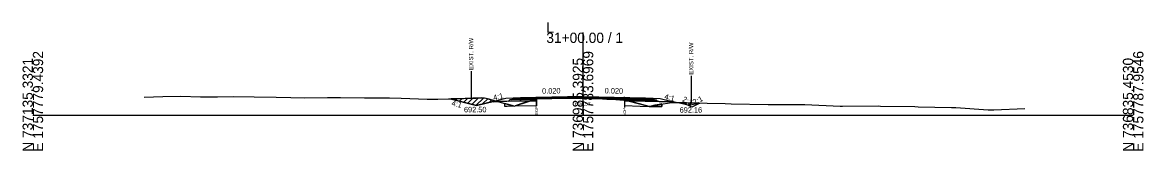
# Model space of a CAD drawing. Extents: x -26 to 4303, y -10 to 9577.
# Drawn here: x 1997.2 to 2302.8, y 990.3 to 1025.3 of the extents above; entities that cross this region are included whole.
import ezdxf

# ---------------------------------------------------------------- set-up
doc = ezdxf.new("R2010")
doc.units = 0
for name, color, linetype in [('Default', 7, 'Continuous'), ('Exist CMT Pavement', 7, 'Continuous'), ('Old_Level_10', 7, 'Continuous'), ('Old_Level_2', 7, 'Continuous'), ('Pattern 1', 7, 'Continuous'), ('Prop CMT Conc Surface', 7, 'Continuous'), ('Prop CMT Concrete Structures', 7, 'Continuous'), ('Prop CMT Concrete Wall', 7, 'Continuous'), ('Prop CMT Pvmt Course 1', 7, 'Continuous'), ('Prop CMT Pvmt Course 1 CG', 7, 'Continuous'), ('Prop CMT Pvmt Course 1 Wedge', 7, 'Continuous'), ('Prop CMT Pvmt Course 2', 7, 'Continuous'), ('Prop CMT Pvmt Course 2 Wedge', 7, 'Continuous'), ('Prop CMT Pvmt Course 3', 7, 'Continuous'), ('Prop CMT Pvmt Surface', 7, 'Continuous'), ('Prop CMT Pvmt Surface Shoulder', 7, 'Continuous'), ('Prop CMT Pvmt Wedge Surface 1', 7, 'Continuous'), ('Prop CMT Pvmt Wedge Surface 2', 7, 'Continuous'), ('Prop CMT Pvmt Wedge Surface 3', 7, 'Continuous'), ('Prop CMT Shld Paved Course 1', 7, 'Continuous'), ('Prop CMT Shld Paved Course 2', 7, 'Continuous'), ('Prop CMT Shld Paved Course 3', 7, 'Continuous'), ('Prop CMT Slope Grass', 7, 'Continuous'), ('Prop CMT Subgrade Earthwork', 7, 'Continuous'), ('Prop Road Sect_ Recs - UC Shallow (Outline)', 7, 'Continuous'), ('Prop Shade Light', 7, 'Continuous'), ('Prop XS DDE Elevations', 7, 'Continuous'), ('Prop XS Ditch Standard Text', 7, 'Continuous'), ('Prop XS Earthwork Shape', 7, 'Continuous'), ('Prop XS Hydro Elevations', 7, 'Continuous'), ('Prop XS SE Text', 7, 'Continuous'), ('Prop XS Side Slope Text', 7, 'Continuous'), ('Prop XS Wedging', 7, 'Continuous'), ('Scratch_Level_9', 7, 'Continuous')]:
    doc.layers.add(name, color=color, linetype=linetype)

msp = doc.modelspace()

# ---------------------------------------------------------------- linework, layer by layer
at = {"layer": 'Exist CMT Pavement'}
for points in [[(2150, 1005.04), (2133, 1004.7)], [(2150, 1005.04), (2167, 1004.7)]]:
    msp.add_lwpolyline(points, dxfattribs=at)
at = {"layer": 'Old_Level_10'}
for p, q in [((2177.43, 1003.29), (2175.43, 1003.39)), ((2179.69, 1002.16), (2177.43, 1003.29)), ((2181.88, 1003.26), (2179.69, 1002.16))]:
    msp.add_line(p, q, dxfattribs=at)
at = {"layer": 'Old_Level_2'}
for p, q in [((2150, 1000), (2150, 1022.49)), ((2150, 1000), (2150, 1022.49)), ((2000, 1000), (2150, 1000)), ((2000, 1000), (2150, 1000)), ((2150, 1000), (2300, 1000)), ((2150, 1000), (2300, 1000))]:
    msp.add_line(p, q, dxfattribs=at)
at = {"layer": 'Pattern 1'}
for p, q in [((2114.12, 1004.41), (2114.12, 1004.42)), ((2115.25, 1004.13), (2115.59, 1004.47)), ((2116.38, 1003.85), (2117.05, 1004.52)), ((2117.51, 1003.56), (2118.51, 1004.56)), ((2118.64, 1003.28), (2119.97, 1004.61)), ((2119.77, 1003), (2121.42, 1004.65)), ((2120.9, 1002.71), (2122.83, 1004.64)), ((2122.72, 1003.12), (2124.03, 1004.43)), ((2124.61, 1003.59), (2125.14, 1004.12)), ((2176.78, 1003.24), (2176.9, 1003.36)), ((2177.92, 1002.96), (2178.28, 1003.33)), ((2179.08, 1002.71), (2179.67, 1003.3)), ((2180.96, 1003.18), (2181.06, 1003.27))]:
    msp.add_line(p, q, dxfattribs=at)
for points in [[(2121, 1002.69), (2125.88, 1003.91), (2124.42, 1004.32), (2123.56, 1004.56), (2123.16, 1004.63), (2122.3, 1004.67), (2119.96, 1004.61), (2115.65, 1004.47), (2114.09, 1004.42)], [(2136.1, 1004.08), (2137.35, 1004.54), (2137.35, 1004.1)], [(2179, 1002.69), (2181.31, 1003.27), (2178.21, 1003.33), (2176.94, 1003.36), (2176.28, 1003.37)]]:
    msp.add_lwpolyline(points, close=True, dxfattribs=at)
at = {"layer": 'Prop CMT Conc Surface'}
for points in [[(2137.35, 1004.53), (2133, 1004.45)], [(2133, 1004.45), (2133, 1004.24)], [(2133, 1004.24), (2137.35, 1004.33)], [(2137.35, 1004.33), (2137.35, 1004.53)], [(2161.34, 1004.35), (2161.34, 1004.56)], [(2161.34, 1004.56), (2167, 1004.45)], [(2167, 1004.24), (2161.34, 1004.35)], [(2167, 1004.45), (2167, 1004.24)]]:
    msp.add_lwpolyline(points, dxfattribs=at)
at = {"layer": 'Prop CMT Concrete Structures'}
for points in [[(2133, 1004.45), (2133, 1004.7)], [(2137.35, 1004.53), (2133, 1004.45)], [(2150, 1004.91), (2137.35, 1004.66)], [(2137.35, 1004.66), (2137.35, 1004.53)], [(2150, 1004.91), (2161.34, 1004.68)], [(2161.34, 1004.68), (2161.34, 1004.56)], [(2161.34, 1004.56), (2167, 1004.45)], [(2167, 1004.45), (2167, 1004.7)]]:
    msp.add_lwpolyline(points, dxfattribs=at)
at = {"layer": 'Prop CMT Pvmt Course 1'}
for points in [[(2137.35, 1004.33), (2133, 1004.24)], [(2133, 1004.24), (2133, 1003.9)], [(2133, 1003.9), (2137.35, 1003.99)], [(2137.35, 1003.99), (2137.35, 1004.33)], [(2161.34, 1004.35), (2167, 1004.24)], [(2161.34, 1004.02), (2161.34, 1004.35)], [(2167, 1003.9), (2161.34, 1004.02)], [(2167, 1004.24), (2167, 1003.9)]]:
    msp.add_lwpolyline(points, dxfattribs=at)
at = {"layer": 'Prop CMT Pvmt Course 1 Wedge'}
for points in [[(2149.82, 1004.57), (2150, 1004.58)], [(2150, 1004.57), (2149.82, 1004.57)], [(2150, 1004.58), (2150, 1004.57)], [(2150, 1004.58), (2150.04, 1004.58), (2151.64, 1004.55), (2151.65, 1004.55), (2151.87, 1004.54), (2154.08, 1004.5), (2154.14, 1004.5), (2156.51, 1004.45), (2156.65, 1004.45), (2158.95, 1004.4), (2159.15, 1004.4), (2159.75, 1004.38), (2160.07, 1004.38), (2160.26, 1004.37), (2160.38, 1004.37), (2160.47, 1004.37), (2160.54, 1004.37), (2160.87, 1004.36), (2160.97, 1004.36), (2161.13, 1004.36), (2161.2, 1004.35), (2161.34, 1004.35)], [(2161.34, 1004.12), (2161.2, 1004.16), (2161.13, 1004.16), (2160.97, 1004.18), (2160.87, 1004.19), (2160.54, 1004.19), (2160.47, 1004.2), (2160.38, 1004.2), (2160.26, 1004.2), (2160.07, 1004.2), (2159.75, 1004.22), (2159.15, 1004.23), (2158.95, 1004.23), (2156.65, 1004.33), (2156.51, 1004.33), (2154.14, 1004.48), (2154.08, 1004.48), (2151.87, 1004.53), (2151.65, 1004.54), (2151.64, 1004.54), (2150.04, 1004.57), (2150, 1004.57)], [(2161.34, 1004.35), (2161.34, 1004.12)]]:
    msp.add_lwpolyline(points, dxfattribs=at)
at = {"layer": 'Prop CMT Pvmt Course 2'}
for points in [[(2133, 1004.7), (2131, 1004.66), (2130.74, 1004.4)], [(2130.74, 1004.4), (2133, 1004.45)], [(2133, 1004.45), (2133, 1004.7)], [(2167, 1004.7), (2169, 1004.66), (2169.26, 1004.4)], [(2167, 1004.45), (2167, 1004.7)], [(2169.26, 1004.4), (2167, 1004.45)]]:
    msp.add_lwpolyline(points, dxfattribs=at)
at = {"layer": 'Prop CMT Pvmt Course 2 Wedge'}
for points in [[(2131, 1004.66), (2129, 1004.5), (2121, 1002.5), (2113.4, 1004.4)], [(2169, 1004.66), (2171, 1004.5), (2175.43, 1003.39)]]:
    msp.add_lwpolyline(points, dxfattribs=at)
at = {"layer": 'Prop CMT Pvmt Course 3'}
for points in [[(2133, 1004.45), (2130.74, 1004.4), (2130.53, 1004.19)], [(2130.53, 1004.19), (2133, 1004.24)], [(2133, 1004.24), (2133, 1004.45)], [(2167, 1004.45), (2169.26, 1004.4), (2169.47, 1004.19)], [(2167, 1004.24), (2167, 1004.45)], [(2169.47, 1004.19), (2167, 1004.24)]]:
    msp.add_lwpolyline(points, dxfattribs=at)
at = {"layer": 'Prop CMT Pvmt Surface'}
for points in [[(2150, 1004.79), (2133, 1004.45)], [(2133, 1004.45), (2133, 1004.7)], [(2150, 1004.79), (2167, 1004.45)], [(2167, 1004.45), (2167, 1004.7)]]:
    msp.add_lwpolyline(points, dxfattribs=at)
at = {"layer": 'Prop CMT Pvmt Surface Shoulder'}
for points in [[(2137.35, 1004.54), (2137.37, 1004.55), (2137.56, 1004.55), (2137.85, 1004.56), (2137.95, 1004.56), (2138.34, 1004.57), (2138.5, 1004.57), (2138.98, 1004.57), (2139.14, 1004.57), (2139.49, 1004.57), (2141.64, 1004.58), (2141.92, 1004.58), (2144.14, 1004.61), (2144.35, 1004.6), (2146.64, 1004.58), (2148.57, 1004.58), (2149.37, 1004.58), (2149.42, 1004.58), (2149.66, 1004.58), (2149.77, 1004.58), (2150, 1004.57)], [(2150, 1004.57), (2150.04, 1004.57), (2151.64, 1004.54), (2151.65, 1004.54), (2151.87, 1004.53), (2154.08, 1004.48), (2154.14, 1004.48), (2156.51, 1004.33), (2156.65, 1004.33), (2158.95, 1004.23), (2159.15, 1004.23), (2159.75, 1004.22), (2160.07, 1004.2), (2160.26, 1004.2), (2160.38, 1004.2), (2160.47, 1004.2), (2160.54, 1004.19), (2160.87, 1004.19), (2160.97, 1004.18), (2161.13, 1004.16), (2161.2, 1004.16), (2161.34, 1004.12)]]:
    msp.add_lwpolyline(points, dxfattribs=at)
at = {"layer": 'Prop CMT Pvmt Wedge Surface 1'}
for p, q in [((2133.02, 1003.78), (2125.53, 1003.63)), ((2137.35, 1003.87), (2133.02, 1003.78)), ((2161.35, 1003.89), (2166.98, 1003.78)), ((2166.98, 1003.78), (2174.47, 1003.63))]:
    msp.add_line(p, q, dxfattribs=at)
for points in [[(2137.35, 1003.87), (2137.35, 1004.54)], [(2161.35, 1003.89), (2161.34, 1004.12)]]:
    msp.add_lwpolyline(points, dxfattribs=at)
at = {"layer": 'Prop CMT Pvmt Wedge Surface 2'}
for points in [[(2137.35, 1004.66), (2137.37, 1004.66), (2137.56, 1004.66), (2137.85, 1004.67), (2137.95, 1004.67), (2138.34, 1004.68), (2138.5, 1004.68), (2138.98, 1004.69), (2139.14, 1004.69), (2139.49, 1004.7), (2141.64, 1004.74), (2141.92, 1004.75), (2144.14, 1004.79), (2144.35, 1004.8), (2146.64, 1004.84), (2148.57, 1004.88), (2149.37, 1004.9), (2149.42, 1004.9), (2149.66, 1004.9), (2149.77, 1004.91), (2150, 1004.91)], [(2150, 1004.79), (2149.77, 1004.78), (2149.66, 1004.78), (2149.42, 1004.77), (2149.37, 1004.77), (2148.57, 1004.76), (2146.64, 1004.72), (2144.35, 1004.67), (2144.14, 1004.67), (2141.92, 1004.62), (2141.64, 1004.62), (2139.49, 1004.58), (2139.14, 1004.57), (2139.01, 1004.57), (2138.98, 1004.57), (2138.5, 1004.57), (2138.34, 1004.57), (2137.95, 1004.56), (2137.85, 1004.56), (2137.56, 1004.55), (2137.37, 1004.55), (2137.35, 1004.54)], [(2137.35, 1004.54), (2137.35, 1004.66)], [(2150, 1004.91), (2150, 1004.79)], [(2150, 1004.91), (2150.04, 1004.91), (2151.64, 1004.88), (2151.65, 1004.88), (2151.87, 1004.87), (2154.08, 1004.83), (2154.14, 1004.83), (2156.51, 1004.78), (2156.65, 1004.78), (2158.95, 1004.73), (2159.15, 1004.73), (2159.75, 1004.72), (2160.07, 1004.71), (2160.26, 1004.71), (2160.38, 1004.7), (2160.47, 1004.7), (2160.54, 1004.7), (2160.87, 1004.69), (2160.97, 1004.69), (2161.13, 1004.69), (2161.2, 1004.69), (2161.34, 1004.68)], [(2161.34, 1004.56), (2161.2, 1004.56), (2161.13, 1004.56), (2160.97, 1004.57), (2160.87, 1004.57), (2160.54, 1004.58), (2160.47, 1004.58), (2160.38, 1004.58), (2160.26, 1004.58), (2160.07, 1004.59), (2159.75, 1004.59), (2159.15, 1004.6), (2158.95, 1004.61), (2156.65, 1004.65), (2156.51, 1004.66), (2154.14, 1004.7), (2154.08, 1004.7), (2151.87, 1004.75), (2151.65, 1004.75), (2151.64, 1004.75), (2150.04, 1004.79), (2150, 1004.79)], [(2161.34, 1004.68), (2161.34, 1004.56)]]:
    msp.add_lwpolyline(points, dxfattribs=at)
at = {"layer": 'Prop CMT Pvmt Wedge Surface 3'}
for points in [[(2150, 1004.58), (2149.82, 1004.57), (2149.77, 1004.58), (2149.66, 1004.58), (2149.42, 1004.58), (2149.37, 1004.58), (2148.57, 1004.58), (2146.64, 1004.58), (2144.35, 1004.6), (2144.14, 1004.61), (2141.92, 1004.58), (2141.64, 1004.58), (2139.49, 1004.57), (2139.14, 1004.57), (2139.01, 1004.57)], [(2139.01, 1004.57), (2139.14, 1004.57)], [(2139.14, 1004.57), (2139.49, 1004.58), (2141.64, 1004.62), (2141.92, 1004.62), (2144.14, 1004.67), (2144.35, 1004.67), (2146.64, 1004.72), (2148.57, 1004.76), (2149.37, 1004.77), (2149.42, 1004.77), (2149.66, 1004.78), (2149.77, 1004.78), (2150, 1004.79)], [(2150, 1004.79), (2150, 1004.58)], [(2150, 1004.79), (2150.04, 1004.79), (2151.64, 1004.75), (2151.65, 1004.75), (2151.87, 1004.75), (2154.08, 1004.7), (2154.14, 1004.7), (2156.51, 1004.66), (2156.65, 1004.65), (2158.95, 1004.61), (2159.15, 1004.6), (2159.75, 1004.59), (2160.07, 1004.59), (2160.26, 1004.58), (2160.38, 1004.58), (2160.47, 1004.58), (2160.54, 1004.58), (2160.87, 1004.57), (2160.97, 1004.57), (2161.13, 1004.56), (2161.2, 1004.56), (2161.34, 1004.56)], [(2161.34, 1004.35), (2161.2, 1004.35), (2161.13, 1004.36), (2160.97, 1004.36), (2160.87, 1004.36), (2160.54, 1004.37), (2160.47, 1004.37), (2160.38, 1004.37), (2160.26, 1004.37), (2160.07, 1004.38), (2159.75, 1004.38), (2159.15, 1004.4), (2158.95, 1004.4), (2156.65, 1004.45), (2156.51, 1004.45), (2154.14, 1004.5), (2154.08, 1004.5), (2151.87, 1004.54), (2151.65, 1004.55), (2151.64, 1004.55), (2150.04, 1004.58), (2150, 1004.58)], [(2161.34, 1004.56), (2161.34, 1004.35)]]:
    msp.add_lwpolyline(points, dxfattribs=at)
at = {"layer": 'Prop CMT Shld Paved Course 1'}
for points in [[(2133, 1004.24), (2133, 1004.7)], [(2150, 1004.58), (2133, 1004.24)], [(2150, 1004.58), (2167, 1004.24)], [(2167, 1004.24), (2167, 1004.7)]]:
    msp.add_lwpolyline(points, dxfattribs=at)
at = {"layer": 'Prop CMT Shld Paved Course 2'}
for points in [[(2133, 1004.7), (2131, 1004.66)], [(2167, 1004.7), (2169, 1004.66)]]:
    msp.add_lwpolyline(points, dxfattribs=at)
at = {"layer": 'Prop CMT Shld Paved Course 3'}
for points in [[(2150, 1005.04), (2133, 1004.7)], [(2133, 1004.7), (2133, 1004.45)], [(2133, 1004.45), (2137.35, 1004.53)], [(2137.35, 1004.66), (2150, 1004.91)], [(2137.35, 1004.53), (2137.35, 1004.66)], [(2150, 1004.79), (2150, 1005.04)], [(2150, 1005.04), (2167, 1004.7)], [(2150, 1004.91), (2150, 1004.79), (2150, 1004.79)], [(2161.34, 1004.68), (2150, 1004.91)], [(2161.34, 1004.56), (2161.34, 1004.68)], [(2167, 1004.45), (2161.34, 1004.56)], [(2167, 1004.7), (2167, 1004.45)]]:
    msp.add_lwpolyline(points, dxfattribs=at)
at = {"layer": 'Prop CMT Slope Grass'}
msp.add_lwpolyline([(2030.35, 1004.86), (2035.43, 1005.11), (2040.35, 1005.18), (2045.73, 1005.02), (2050.36, 1005.02), (2054.74, 1005.05), (2060.36, 1005.02), (2066.32, 1004.88), (2070.37, 1004.8), (2074.19, 1004.72), (2080.37, 1004.81), (2083.92, 1004.79), (2090.38, 1004.72), (2097.21, 1004.67), (2100.38, 1004.62), (2107.51, 1004.33), (2110.39, 1004.3), (2120.89, 1004.64), (2122.81, 1004.68), (2123.52, 1004.57), (2131.27, 1002.41), (2135.48, 1003.85), (2137.37, 1004.55), (2137.95, 1004.56), (2138.5, 1004.57), (2139.14, 1004.57), (2139.49, 1004.57), (2141.92, 1004.58), (2144.35, 1004.6), (2146.64, 1004.58), (2148.57, 1004.58), (2149.42, 1004.58), (2150.04, 1004.57), (2151.87, 1004.53), (2154.14, 1004.48), (2156.65, 1004.33), (2159.15, 1004.23), (2159.75, 1004.22), (2160.38, 1004.2), (2160.87, 1004.19), (2161.2, 1004.16), (2165.41, 1003.03), (2168.08, 1002.35), (2170.79, 1002.92), (2174.15, 1003.41), (2188.77, 1003.12), (2190.43, 1003.08), (2200.44, 1002.88), (2208.89, 1002.91), (2210.44, 1002.92), (2220.13, 1002.44), (2220.45, 1002.43), (2220.78, 1002.44), (2230.45, 1002.52), (2231.08, 1002.47), (2240.46, 1002.31), (2241.38, 1002.29), (2250.46, 1002.11), (2251.68, 1002.09), (2260.47, 1001.47), (2261.98, 1001.47), (2270.47, 1001.8)], dxfattribs=at)
at = {"layer": 'Prop CMT Subgrade Earthwork'}
for points in [[(2133, 1004.24), (2130.53, 1004.19), (2130.03, 1004.18), (2129.69, 1003.84)], [(2129.69, 1003.84), (2133, 1003.9)], [(2133, 1003.9), (2133, 1004.24)], [(2167, 1004.24), (2169.47, 1004.19), (2169.97, 1004.18), (2170.31, 1003.84)], [(2167, 1003.9), (2167, 1004.24)], [(2170.31, 1003.84), (2167, 1003.9)]]:
    msp.add_lwpolyline(points, dxfattribs=at)
at = {"layer": 'Prop Road Sect_ Recs - UC Shallow (Outline)'}
for points in [[(2128.64, 1002.43), (2131.03, 1002.48), (2128.62, 1003.15)], [(2131.5, 1002.49), (2137.35, 1002.6), (2137.35, 1004.1), (2136.1, 1004.08), (2133.61, 1003.21)], [(2161.34, 1002.62), (2165.6, 1002.44), (2168.08, 1002.35), (2165.41, 1003.03), (2161.34, 1004.12)], [(2171.5, 1003.03), (2171.52, 1002.36), (2168.08, 1002.35), (2170.87, 1002.93)]]:
    msp.add_lwpolyline(points, close=True, dxfattribs=at)
at = {"layer": 'Prop Shade Light'}
for p, q in [((2129.91, 1002.79), (2128.62, 1003.15)), ((2130.3, 1002.68), (2129.91, 1002.79)), ((2131.03, 1002.48), (2130.3, 1002.68)), ((2137.35, 1004.1), (2136.1, 1004.08)), ((2137.35, 1002.6), (2137.35, 1004.1)), ((2161.75, 1004.01), (2161.34, 1004.02)), ((2161.34, 1004.02), (2161.34, 1002.62)), ((2171.52, 1002.36), (2171.5, 1003.03)), ((2129.3, 1002.44), (2131.03, 1002.48)), ((2170.83, 1002.36), (2171.52, 1002.36))]:
    msp.add_line(p, q, dxfattribs=at)
for points in [[(2128.62, 1003.15), (2128.64, 1002.43), (2129.3, 1002.44)], [(2133.3, 1003.1), (2131.5, 1002.49), (2137.35, 1002.6)], [(2136.1, 1004.08), (2134.24, 1003.42), (2133.3, 1003.1)], [(2161.34, 1004.02), (2161.34, 1004.02)], [(2168.08, 1002.35), (2165.41, 1003.03), (2161.75, 1004.01)], [(2171.5, 1003.03), (2170.78, 1002.91), (2169.57, 1002.66), (2168.57, 1002.46)], [(2161.34, 1002.62), (2165.6, 1002.44), (2168.08, 1002.35)], [(2168.57, 1002.46), (2168.08, 1002.35), (2168.79, 1002.36)], [(2168.79, 1002.36), (2169.55, 1002.36), (2170.83, 1002.36)]]:
    msp.add_lwpolyline(points, dxfattribs=at)
at = {"layer": 'Prop XS DDE Elevations'}
for points in [[(2122.81, 1004.68), (2123.52, 1004.57), (2126.25, 1003.81), (2125.53, 1003.63), (2121, 1002.5), (2113.4, 1004.4), (2120.89, 1004.64)], [(2126.25, 1003.81), (2125.53, 1003.63), (2126.8, 1003.66)], [(2131.27, 1002.41), (2135.42, 1003.83), (2133.02, 1003.78), (2126.8, 1003.66)], [(2137.35, 1003.87), (2137.35, 1004.54), (2135.48, 1003.85), (2135.42, 1003.83)], [(2137.37, 1004.55), (2137.56, 1004.55), (2137.65, 1004.56)], [(2137.85, 1004.56), (2137.95, 1004.56), (2137.65, 1004.56)], [(2138.34, 1004.57), (2138.5, 1004.57), (2137.95, 1004.56)], [(2138.5, 1004.57), (2138.98, 1004.57), (2139.14, 1004.57)], [(2141.64, 1004.58), (2141.92, 1004.58), (2139.49, 1004.57)], [(2141.92, 1004.58), (2144.14, 1004.61), (2144.35, 1004.6)], [(2149.37, 1004.58), (2149.42, 1004.58), (2148.57, 1004.58)], [(2150, 1004.57), (2150.04, 1004.57), (2149.42, 1004.58), (2149.66, 1004.58), (2149.77, 1004.58)], [(2150.04, 1004.57), (2151.64, 1004.54), (2151.87, 1004.53)], [(2156.51, 1004.33), (2156.65, 1004.33), (2154.14, 1004.48)], [(2159.75, 1004.22), (2160.38, 1004.2), (2160.26, 1004.2), (2160.07, 1004.2)], [(2160.47, 1004.2), (2160.54, 1004.19), (2160.87, 1004.19), (2160.38, 1004.2)], [(2161.13, 1004.16), (2161.2, 1004.16), (2160.87, 1004.19), (2160.97, 1004.18)], [(2161.34, 1004.12), (2162.26, 1003.87), (2161.35, 1003.89)], [(2174.15, 1003.41), (2175.43, 1003.39), (2174.47, 1003.63), (2166.98, 1003.78), (2162.26, 1003.87), (2165.41, 1003.03), (2168.08, 1002.35), (2170.79, 1002.92)]]:
    msp.add_lwpolyline(points, close=True, dxfattribs=at)
at = {"layer": 'Prop XS Ditch Standard Text'}
for p, q in [((2119.48, 1012), (2119.48, 1004.6)), ((2179.48, 1010.71), (2179.48, 1003.31)), ((2137.35, 1004.54), (2137.35, 1002.49)), ((2161.34, 1004.12), (2161.34, 1002.07))]:
    msp.add_line(p, q, dxfattribs=at)
at = {"layer": 'Prop XS Earthwork Shape'}
msp.add_lwpolyline([(2181.88, 1003.26), (2179.69, 1002.16), (2177.43, 1003.29), (2175.43, 1003.39)], close=True, dxfattribs=at)
at = {"layer": 'Prop XS Wedging'}
for p, q in [((2137.35, 1004.54), (2137.35, 1004.95)), ((2137.35, 1004.66), (2137.35, 1004.54)), ((2150.06, 1004.79), (2149.86, 1004.58)), ((2149.86, 1004.58), (2150.06, 1004.79)), ((2150.06, 1004.79), (2149.86, 1004.58)), ((2149.86, 1004.58), (2150.04, 1004.57)), ((2150.06, 1004.79), (2161.34, 1004.56)), ((2161.34, 1004.56), (2150.06, 1004.79)), ((2161.34, 1004.12), (2161.34, 1004.97)), ((2161.34, 1004.56), (2161.34, 1004.68)), ((2161.34, 1004.12), (2161.34, 1004.56))]:
    msp.add_line(p, q, dxfattribs=at)
for points in [[(2150, 1004.91), (2133, 1004.57)], [(2150, 1004.91), (2150, 1004.91), (2137.35, 1004.66)], [(2137.35, 1004.54), (2137.37, 1004.55), (2137.95, 1004.56), (2138.5, 1004.57), (2139.14, 1004.57), (2139.49, 1004.57), (2141.92, 1004.58), (2144.35, 1004.6), (2146.64, 1004.58), (2148.57, 1004.58), (2149.42, 1004.58), (2149.86, 1004.58)], [(2150, 1004.91), (2167, 1004.57)], [(2161.34, 1004.68), (2150, 1004.91), (2150, 1004.91)], [(2150.04, 1004.57), (2151.87, 1004.53), (2154.14, 1004.48), (2156.65, 1004.33), (2159.15, 1004.23), (2159.75, 1004.22), (2160.38, 1004.2), (2160.87, 1004.19), (2161.2, 1004.16), (2161.34, 1004.12)], [(2150.06, 1004.79), (2167, 1004.45)]]:
    msp.add_lwpolyline(points, dxfattribs=at)
at = {"layer": 'Scratch_Level_9'}
for p, q in [((2161.34, 1004.12), (2161.34, 1004.02)), ((2161.75, 1004.01), (2161.34, 1004.12)), ((2161.34, 1004.02), (2161.75, 1004.01))]:
    msp.add_line(p, q, dxfattribs=at)

# ---------------------------------------------------------------- texts
at = {"layer": 'Default'}
msp.add_text('-', height=0.0001, dxfattribs=at).set_placement((2000, 1000))
at = {"layer": 'Old_Level_2'}
for s, p in [('L', (2140, 1022.49)), ('L', (2140, 1022.49)), ('31+00.00 / 1', (2140, 1019.69)), ('31+00.00 / 1', (2140, 1019.69))]:
    msp.add_text(s, height=2.8, dxfattribs=at).set_placement(p)
for s, p in [('N 737135.3321', (2000, 990)), ('N 737135.3321', (2000, 990)), ('E 1757779.4392', (2002.8, 990)), ('E 1757779.4392', (2002.8, 990)), ('N 736985.3925', (2150, 990)), ('N 736985.3925', (2150, 990)), ('E 1757783.6969', (2152.8, 990)), ('E 1757783.6969', (2152.8, 990)), ('N 736835.4530', (2300, 990)), ('N 736835.4530', (2300, 990)), ('E 1757787.9546', (2302.8, 990)), ('E 1757787.9546', (2302.8, 990))]:
    msp.add_text(s, height=2.8, rotation=90, dxfattribs=at).set_placement(p)
at = {"layer": 'Prop CMT Concrete Wall'}
for rotation, p in [(334.1383, (2176.91, 1003.82)), (25.8617, (2180.34, 1002.74))]:
    msp.add_text('2:1', height=1.5, rotation=rotation, dxfattribs=at).set_placement(p)
msp.add_text('692.16', height=1.5, dxfattribs=at).set_placement((2176.35, 1000.66))
at = {"layer": 'Prop CMT Pvmt Course 1 CG'}
msp.add_text('694.57', height=1, dxfattribs=at).set_placement((2147.85, 1002.57))
at = {"layer": 'Prop XS Ditch Standard Text'}
for s, height, p in [('EXIST. R/W', 1.181, (2120.07, 1012.3)), ('EXIST. R/W', 1.181, (2180.07, 1011.01)), ('EOP', 0.787, (2137.74, 1000.09)), ('EOP', 0.787, (2161.74, 999.67))]:
    msp.add_text(s, height=height, rotation=90, dxfattribs=at).set_placement(p)
at = {"layer": 'Prop XS Hydro Elevations'}
msp.add_text('692.50', height=1.5, dxfattribs=at).set_placement((2117.55, 1000.75))
at = {"layer": 'Prop XS SE Text'}
for rotation, p in [(1.1458, (2138.86, 1005.81)), (358.8542, (2155.9, 1005.92))]:
    msp.add_text('0.020', height=1.5, rotation=rotation, dxfattribs=at).set_placement(p)
at = {"layer": 'Prop XS Side Slope Text'}
for rotation, p in [(14.0362, (2125.71, 1003.97)), (345.9638, (2172.1, 1004.4)), (345.9638, (2114.07, 1002.62))]:
    msp.add_text('4:1', height=1.5, rotation=rotation, dxfattribs=at).set_placement(p)

doc.saveas('drawing.dxf')
